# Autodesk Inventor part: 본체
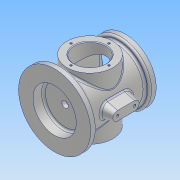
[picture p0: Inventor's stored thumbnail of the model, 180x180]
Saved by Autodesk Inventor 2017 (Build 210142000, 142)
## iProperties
Part Number: 본체
Material: 알루미늄 6061
Document SubType Name: Modeling
Designer: Administrator
Density: 2.7 g/cm^3
Appearance: 알루미늄 - 평지
Mass: 792.322 g
Surface Area: 769.487 cm^2
Volume: 293.453 cm^3
Author: Administrator
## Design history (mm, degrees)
sketch "스케치4"
  geometry: C1 r 55 at (0, 0); 1 further point
  constraints: 1 centre point, 1 coincident
  dimensions: "d9" = 110 diameter of C1
extrude "돌출4" new body sketch "스케치4" distance "d10" = 10; taper "d11" = 0 deg
sketch "스케치5"
  geometry: C1 r 55 at (0, 0) reference; C2 r 40 at (0, 0)
  constraints: 1 centre point, 1 coincident
  dimensions: "d12" = 80 diameter of C2
extrude "돌출5" join sketch "스케치5" distance "d13" = 88; taper "d14" = 0 deg
sketch "스케치6"
  geometry: C1 r 40 at (0, 0) reference; C2 r 47 at (0, 0)
  constraints: 1 centre point, 1 coincident
  dimensions: "d15" = 94 diameter of C2
extrude "돌출6" join sketch "스케치6" distance "d16" = 10; taper "d17" = 0 deg
sketch "스케치7"
  geometry: L1 (54, 129.53)-(54, -154.754); L2 (0, 0)-(143.846, 0); L3 (89, 47)-(54, 47); L4 (54, -47)-(89, -47); L5 (89, -47)-(89, 47); 1 further point
  constraints: 10 end point, 3 point on line, 2 horizontal, 1 parallel, 1 vertical
  dimensions: "d18" = 108 diameter of L2.start L1; "d19" = 70 diameter of L5 L1; "d20" = 94 distance of L4.end L3.start
revolve "회전1" sketch "스케치7" stored, may be unused: angle "d21" = 360 deg
sketch "스케치8"
  geometry: C1 r 35 at (0, 0) reference; C2 r 24 at (0, 0); 1 further point
  constraints: 1 centre point, 1 coincident
  dimensions: "d22" = 48 diameter of C2
extrude "돌출7" cut sketch "스케치8" stored distance "d23" = 0; taper "d24" = 0 deg
sketch "스케치9"
  geometry: C1 r 47 at (0, 0) reference; C2 r 35 at (0, 0)
  constraints: 1 centre point, 1 coincident
  dimensions: "d25" = 70 diameter of C2
extrude "돌출8" cut sketch "스케치9" distance "d26" = 7; taper "d27" = 0 deg
sketch "스케치10"
  geometry: C1 r 35 at (0, 0) reference
sketch "스케치11"
  geometry: C1 r 35 at (0, 0) reference; C2 r 33 at (0, 0)
  constraints: 1 centre point, 1 coincident
  dimensions: "d28" = 66 diameter of C2
extrude "돌출9" cut sketch "스케치11" distance "d29" = 79; taper "d30" = 0 deg
sketch "스케치12"
  geometry: C1 r 33 at (0, 0) reference; C2 r 5 at (0, 0)
  constraints: 1 centre point, 1 coincident
  dimensions: "d31" = 10 diameter of C2
hole "구멍1" sketch "스케치12" at (0, 0) diameter "d32" = 10; stored, may be unused: countersink angle "d36" = 90 deg, drill point angle "d38" = 0 deg; dims "d33" = 6, "d34" = 4, "d35" = 2, "d37" = 8
sketch "스케치13"
  geometry: C1 r 5 at (0, 0) reference; C2 r 5 at (0, 0) reference; C3 r 33 at (0, 0)
  constraints: 1 centre point, 1 coincident
  dimensions: "d39" = 66 diameter of C3
extrude "돌출10" cut sketch "스케치13" distance "d40" = 16; taper "d41" = 0 deg
node "작업 평면1"
node "작업 평면2"
sketch "스케치22"
  geometry: L1 (67, 0)-(41, 0); L2 (67, 7)-(41, 7); L3 (41, -7)-(67, -7); L4 (0, 55)-(0, -55) reference; A1 r 7 centre (67, 0) between (67, -7) and (67, 7); A2 r 7 centre (41, 0) between (41, 7) and (41, -7); 2 further points
  constraints: 8 end point, 4 point on circle, 4 tangent, 2 centre point, 1 horizontal, 1 midpoint, 1 parallel
  dimensions: "d62" = 14 diameter of A2; "d63" = 40 dimension on A2 A1; "d64" = 54 distance from line of L4 point (54, 0)
extrude "돌출12" join sketch "스케치22" stored distance "d65" = 16; taper "d66" = 0 deg
feature "면 기울기2" dims angle "d67" = 15 deg
feature "면 기울기3" dims angle "d68" = 15 deg
feature "면 기울기4" dims angle "d69" = 15 deg
feature "면 기울기5" dims angle "d70" = 15 deg
sketch "스케치23"
  geometry: C1 r 24 at (0, 0) reference; 2 further points
  dimensions: "d71" = 29 distance of C1.centre point (0, 29)
hole "구멍2" sketch "스케치23" at (0, 29) diameter "d72" = 3.242; stored, may be unused: countersink angle "d76" = 90 deg, drill point angle "d78" = 118 deg; dims "d73" = 6, "d74" = 4, "d75" = 2, "d77" = 8
sketch "스케치24"
  geometry: C1 r 35 at (0, 0) reference; 1 further point
  dimensions: "d82" = 40 distance of point (40, 0) C1.centre
hole "구멍3" sketch "스케치24" at (40, 0) diameter "d83" = 3.242; stored, may be unused: countersink angle "d87" = 90 deg, drill point angle "d89" = 118 deg; dims "d84" = 6, "d85" = 4, "d86" = 2, "d88" = 8
sketch "스케치25"
  geometry: L1 (-7, 67)-(-7, 41) reference; L2 (7, 41)-(7, 67) reference; A1 r 7 centre (0, 41) between (-7, 41) and (7, 41) reference; A2 r 7 centre (0, 67) between (7, 67) and (-7, 67) reference; A3 r 7 centre (0, 41) between (-7, 41) and (7, 41) reference; A4 r 7 centre (0, 67) between (7, 67) and (-7, 67) reference; 1 further point
hole "구멍4" sketch "스케치25" at (0, 67), (0, 41) diameter "d93" = 4.134; stored, may be unused: countersink angle "d97" = 90 deg, drill point angle "d99" = 118 deg; dims "d94" = 6, "d95" = 4, "d96" = 2, "d98" = 8
sketch "스케치26"
  geometry: C1 r 55 at (0, 0) reference; C2 r 50 at (0, 0)
  constraints: 1 centre point, 1 coincident, 1 other
  dimensions: "d100" = 100 diameter of C2
feature "엠보싱1" sketch "스케치26" dims "d18" = 108, "d19" = 70, "d20" = 94, "d101" = 0.5, "d102" = 0
fillet "모깎기1" dims "d103" = 3
chamfer "모따기1" distance "d104" = 1; stored, may be unused: second distance "d105" = 2, angle "d106" = 45 deg
fillet "모깎기2" dims "d107" = 3
chamfer "모따기2" distance "d108" = 1; stored, may be unused: second distance "d109" = 2, angle "d110" = 45 deg
node "솔리드2"
pattern_circular "원형 패턴1" dims angle "d80" = 360 deg
mirror "미러1"
pattern_circular "원형 패턴2" dims angle "d91" = 360 deg
node "투영된 루프1"
node "투영된 루프4"
other parameters: "d42" = 55, "d58" = 54
